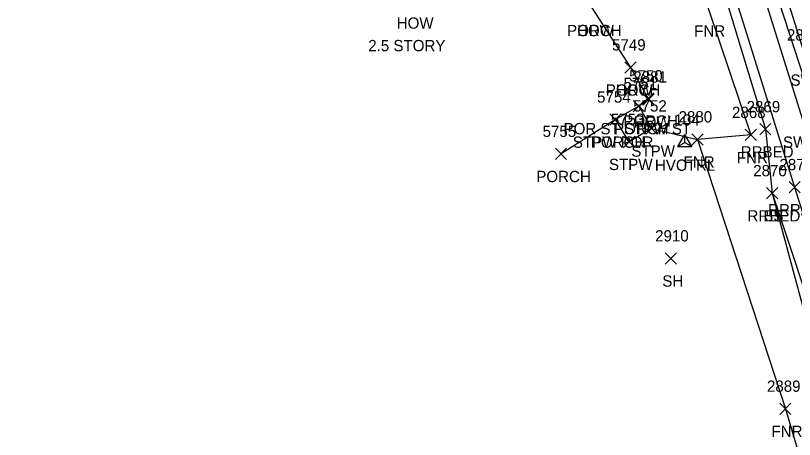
# Model space of a CAD drawing. Extents: x 1462668 to 1465147, y 550359 to 557351.
# Drawn here: x 1464186.6 to 1464324.5, y 553509.3 to 553584.3 of the extents above; entities that cross this region are included whole.
import ezdxf

# ---------------------------------------------------------------- set-up
doc = ezdxf.new("R2010")
doc.units = 0
for name, color, linetype in [('C_A', 7, 'Continuous'), ('C_I', 7, 'Continuous'), ('CPSM', 7, 'Continuous'), ('L_A', 7, 'Continuous'), ('L_C', 7, 'Continuous'), ('L_I', 7, 'Continuous'), ('L_TIC', 7, 'Continuous'), ('LBC', 7, 'Continuous'), ('LBF', 7, 'Continuous'), ('LELB', 7, 'Continuous'), ('Level 6', 7, 'Continuous'), ('LFNC', 7, 'Continuous'), ('R_A', 7, 'Continuous'), ('R_I', 7, 'Continuous'), ('R_TIC', 7, 'Continuous'), ('RR', 7, 'Continuous'), ('RRB', 7, 'Continuous'), ('RSW', 7, 'Continuous')]:
    doc.layers.add(name, color=color, linetype=linetype)

msp = doc.modelspace()

# ---------------------------------------------------------------- linework, layer by layer
at = {"layer": 'CPSM'}
for p, q in [((1464303.86, 553561.11), (1464305.11, 553563.28)), ((1464306.36, 553561.11), (1464305.11, 553563.28)), ((1464305.11, 553561.83), (1464305.11, 553563.28)), ((1464303.86, 553561.11), (1464305.11, 553561.83)), ((1464303.86, 553561.11), (1464306.36, 553561.11)), ((1464305.11, 553561.83), (1464305.11, 553561.83)), ((1464305.11, 553561.83), (1464306.36, 553561.11))]:
    msp.add_line(p, q, dxfattribs=at)
at = {"layer": 'L_TIC'}
for points in [[(1464294.49, 553574.14), (1464296.49, 553576.14)], [(1464296.49, 553574.14), (1464294.49, 553576.14)], [(1464294.49, 553574.14), (1464296.49, 553576.14)], [(1464296.49, 553574.14), (1464294.49, 553576.14)], [(1464297.6, 553568.65), (1464299.6, 553570.65)], [(1464299.6, 553568.65), (1464297.6, 553570.65)], [(1464297.69, 553568.46), (1464299.69, 553570.46)], [(1464299.69, 553568.46), (1464297.69, 553570.46)], [(1464295.94, 553567.3), (1464297.94, 553569.3)], [(1464297.94, 553567.3), (1464295.94, 553569.3)], [(1464295.94, 553567.3), (1464297.94, 553569.3)], [(1464297.94, 553567.3), (1464295.94, 553569.3)], [(1464291.83, 553564.91), (1464293.83, 553566.91)], [(1464293.83, 553564.91), (1464291.83, 553566.91)], [(1464291.83, 553564.91), (1464293.83, 553566.91)], [(1464293.83, 553564.91), (1464291.83, 553566.91)], [(1464298.23, 553563.33), (1464300.23, 553565.33)], [(1464300.23, 553563.33), (1464298.23, 553565.33)], [(1464315.78, 553562.18), (1464317.78, 553564.18)], [(1464317.78, 553562.18), (1464315.78, 553564.18)], [(1464294.27, 553560.96), (1464296.27, 553562.96)], [(1464296.27, 553560.96), (1464294.27, 553562.96)], [(1464306.34, 553561.4), (1464308.34, 553563.4)], [(1464308.34, 553561.4), (1464306.34, 553563.4)], [(1464282.18, 553558.83), (1464284.18, 553560.83)], [(1464284.18, 553558.83), (1464282.18, 553560.83)], [(1464319.57, 553551.86), (1464321.57, 553553.86)], [(1464321.57, 553551.86), (1464319.57, 553553.86)], [(1464301.63, 553540.32), (1464303.63, 553542.32)], [(1464303.63, 553540.32), (1464301.63, 553542.32)], [(1464321.91, 553513.69), (1464323.91, 553515.69)], [(1464323.91, 553513.69), (1464321.91, 553515.69)]]:
    msp.add_lwpolyline(points, dxfattribs=at)
at = {"layer": 'LBC'}
for points in [[(1464256.69, 553587.01), (1464279.36, 553600.54), (1464285.88, 553590.34), (1464288.62, 553585.68), (1464295.49, 553575.14)], [(1464298.69, 553569.46), (1464296.94, 553568.3)]]:
    msp.add_lwpolyline(points, dxfattribs=at)
at = {"layer": 'LBF'}
for points in [[(1464295.49, 553575.14), (1464298.6, 553569.65)], [(1464298.6, 553569.65), (1464298.69, 553569.46)], [(1464296.94, 553568.3), (1464292.83, 553565.91), (1464283.18, 553559.83)], [(1464296.94, 553568.3), (1464299.23, 553564.33), (1464295.27, 553561.96), (1464292.83, 553565.91)]]:
    msp.add_lwpolyline(points, dxfattribs=at)
at = {"layer": 'LELB'}
msp.add_lwpolyline([(1464320.57, 553552.86), (1464335.76, 553496.58), (1464351.01, 553439.58), (1464352, 553433.56), (1464356.91, 553435.89), (1464366.09, 553404.9), (1464375.79, 553365.63), (1464378.91, 553354.3), (1464392.5, 553314.3), (1464410.74, 553264.08), (1464424.65, 553220.18), (1464446.71, 553164.77), (1464462.56, 553121.26), (1464478.7, 553079.34), (1464487.04, 553051.03), (1464509.44, 553004.95), (1464519.17, 552979.76), (1464533.37, 552948.39), (1464548.85, 552915.73), (1464568.29, 552875.06), (1464587.07, 552834.38)], dxfattribs=at)
at = {"layer": 'Level 6'}
msp.add_lwpolyline([(1464231.38, 553705.2), (1464228.92, 553696.96), (1464226.46, 553688.72), (1464238.09, 553674.62), (1464252.11, 553642.55), (1464252.72, 553641.92), (1464263.6, 553624.96), (1464264.3, 553623.99), (1464242.39, 553609.62), (1464246.27, 553604.45), (1464246.88, 553602.26), (1464256.69, 553587.01), (1464279.36, 553600.54), (1464285.88, 553590.34), (1464288.62, 553585.68), (1464295.49, 553575.14), (1464298.6, 553569.65), (1464296.94, 553568.3), (1464299.23, 553564.33), (1464307.34, 553562.4), (1464322.91, 553514.69), (1464338.05, 553463.49)], dxfattribs=at)
at = {"layer": 'LFNC'}
msp.add_lwpolyline([(1464257.84, 553674.25), (1464270.31, 553653.93), (1464279.1, 553640.79), (1464291.45, 553620.03), (1464309.23, 553585.61), (1464316.78, 553563.18), (1464307.34, 553562.4), (1464322.91, 553514.69), (1464338.05, 553463.49), (1464345.71, 553436.5), (1464352.27, 553411.5)], dxfattribs=at)
at = {"layer": 'R_TIC'}
for points in [[(1464318.37, 553563.19), (1464320.37, 553565.19)], [(1464320.37, 553563.19), (1464318.37, 553565.19)], [(1464323.56, 553552.94), (1464325.56, 553554.94)], [(1464325.56, 553552.94), (1464323.56, 553554.94)], [(1464319.57, 553551.86), (1464321.57, 553553.86)], [(1464321.57, 553551.86), (1464319.57, 553553.86)]]:
    msp.add_lwpolyline(points, dxfattribs=at)
at = {"layer": 'RR'}
for points in [[(1464154.28, 554097.88), (1464165.91, 554060.67), (1464179.18, 554017.63), (1464192.39, 553975.37), (1464204.49, 553936.13), (1464218.06, 553892.73), (1464235.46, 553837.34), (1464253.11, 553781.21), (1464266.29, 553739.57), (1464273.1, 553717.55), (1464293.09, 553653.68), (1464309.88, 553600.87), (1464324.56, 553553.94), (1464342.17, 553498.07)], [(1464159.2, 554098.67), (1464170.62, 554062.01), (1464183.92, 554019.07), (1464196.89, 553977.39), (1464209.21, 553938.08), (1464222.64, 553894.36), (1464240.12, 553839.14), (1464257.79, 553782.62), (1464270.96, 553740.9), (1464277.93, 553719.15), (1464297.82, 553655.4), (1464314.57, 553602.42), (1464329.23, 553555.38), (1464346.96, 553499.53)]]:
    msp.add_lwpolyline(points, dxfattribs=at)
at = {"layer": 'RRB'}
for points in [[(1464161.71, 554099.45), (1464173.81, 554063.1), (1464186.02, 554019.88), (1464199.38, 553978.33), (1464209.4, 553949.71), (1464214.23, 553929.59), (1464224.65, 553895.04), (1464242.27, 553839.51), (1464259.34, 553783.49), (1464272.85, 553741.47), (1464279.49, 553719.79), (1464299.3, 553656.24), (1464316.44, 553603.18), (1464331.59, 553556.58), (1464345.31, 553519.91), (1464352.28, 553501.12)], [(1464151.79, 554097.77), (1464163.73, 554059.7), (1464177.17, 554017.63), (1464190.46, 553974.22), (1464202.51, 553935.73), (1464215.79, 553891.79), (1464232.83, 553836.51), (1464250.85, 553780.59), (1464262.35, 553738.51), (1464269.73, 553716.51), (1464275.24, 553698.12), (1464287.03, 553660.88), (1464293.5, 553639.16), (1464306.31, 553607.26), (1464308.6, 553599.83), (1464319.37, 553564.19), (1464320.57, 553552.86), (1464339.05, 553497.3)]]:
    msp.add_lwpolyline(points, dxfattribs=at)
at = {"layer": 'RSW'}
msp.add_lwpolyline([(1464297.07, 553670.96), (1464301.31, 553656.95), (1464318.09, 553603.62), (1464326.46, 553576.9), (1464330.58, 553565.91), (1464334.61, 553558.46)], dxfattribs=at)

# ---------------------------------------------------------------- texts
at = {"layer": 'C_A'}
msp.add_text('HVCTRL', height=2, dxfattribs=at).set_placement((1464299.81, 553556.83))
at = {"layer": 'C_I'}
msp.add_text('104', height=2, dxfattribs=at).set_placement((1464303.24, 553564.83))
at = {"layer": 'L_A'}
for s, p in [('HOW', (1464254.08, 553582.01)), ('PORCH', (1464284.25, 553580.68)), ('HOW', (1464286.01, 553580.68)), ('FNR', (1464306.76, 553580.61)), ('PORCH', (1464291.11, 553570.14)), ('HOW', (1464292.88, 553570.14)), ('PORCH', (1464294.22, 553564.65)), ('HOW', (1464296.07, 553564.46)), ('POR ST STPW ST', (1464283.63, 553563.3)), ('PORCH', (1464292.57, 553563.3)), ('STPW POR', (1464285.28, 553560.91)), ('PORCH', (1464288.46, 553560.91)), ('STPW', (1464295.63, 553559.33)), ('FNR', (1464304.88, 553557.4)), ('FNR', (1464314.32, 553558.18)), ('STPW', (1464291.67, 553556.96)), ('PORCH', (1464278.8, 553554.83)), ('BS', (1464319.01, 553547.86)), ('SH', (1464301.12, 553536.32)), ('FNR', (1464320.45, 553509.69))]:
    msp.add_text(s, height=2, dxfattribs=at).set_placement(p)
at = {"layer": 'L_C'}
msp.add_text('2.5 STORY', height=2, dxfattribs=at).set_placement((1464249.04, 553578.01))
at = {"layer": 'L_I'}
for s, p in [('5749', (1464292.22, 553578.14)), ('5749', (1464292.22, 553578.14)), ('5750', (1464295.25, 553572.65)), ('5751', (1464294.25, 553571.3)), ('5751', (1464294.25, 553571.3)), ('2881', (1464295.99, 553572.46)), ('5754', (1464289.57, 553568.91)), ('5754', (1464289.57, 553568.91)), ('5752', (1464295.97, 553567.33)), ('2868', (1464313.47, 553566.18)), ('5753', (1464292.01, 553564.96)), ('2880', (1464304, 553565.4)), ('5755', (1464279.92, 553562.83)), ('2870', (1464317.22, 553555.86)), ('2910', (1464299.85, 553544.32)), ('2889', (1464319.65, 553517.69))]:
    msp.add_text(s, height=2, dxfattribs=at).set_placement(p)
at = {"layer": 'R_A'}
for s, p in [('SWP', (1464323.82, 553571.9)), ('SWP TS1 ST', (1464322.49, 553560.91)), ('RRBED', (1464315.01, 553559.19)), ('RRBED', (1464316.21, 553547.86)), ('RRRAIL', (1464319.85, 553548.94))]:
    msp.add_text(s, height=2, dxfattribs=at).set_placement(p)
at = {"layer": 'R_I'}
for s, p in [('2842', (1464323.2, 553579.9)), ('2869', (1464316.05, 553567.19)), ('2871', (1464321.86, 553556.94)), ('2870', (1464317.22, 553555.86))]:
    msp.add_text(s, height=2, dxfattribs=at).set_placement(p)

doc.saveas('drawing.dxf')
